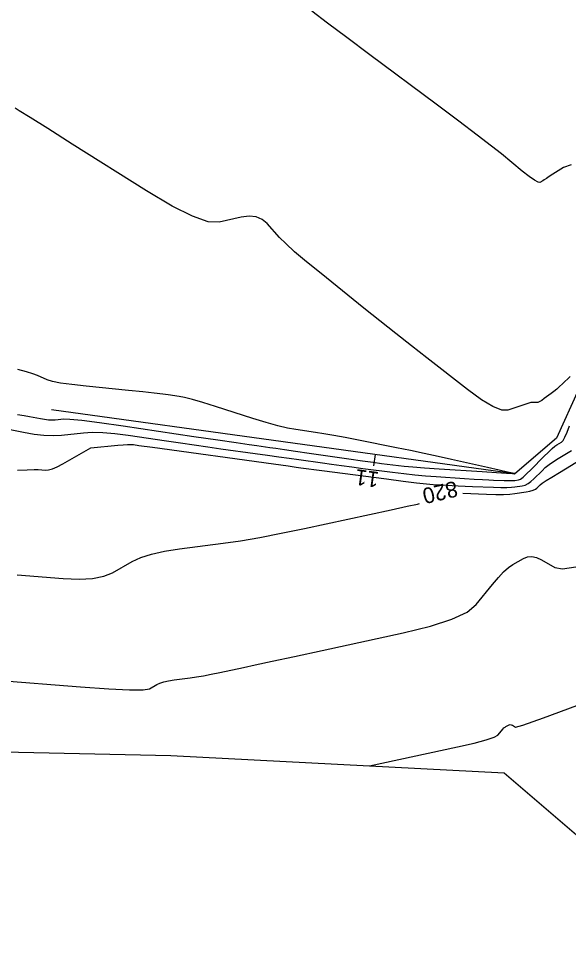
# Model space of a CAD drawing. Extents: x 1715724 to 1716561, y 394063 to 395906.
# Drawn here: x 1716135.4 to 1716184.2, y 394602.7 to 394685.4 of the extents above; entities that cross this region are included whole.
import ezdxf

# ---------------------------------------------------------------- set-up
doc = ezdxf.new("R2010")
doc.units = 0
for name, color, linetype in [('DT_X_Contour_Major', 7, 'Continuous'), ('DT_X_Contour_Minor', 7, 'Continuous'), ('DT_X_TIN_Hull', 7, 'Continuous'), ('GE_P_CL_10', 7, 'Continuous')]:
    doc.layers.add(name, color=color, linetype=linetype)

msp = doc.modelspace()

# ---------------------------------------------------------------- linework, layer by layer
at = {"layer": 'DT_X_Contour_Major'}
for points in [[(1716174.82, 394643.363), (1716176.907, 394643.286), (1716177.734, 394643.265), (1716178.431, 394643.266), (1716178.998, 394643.289), (1716179.437, 394643.336), (1716180.433, 394643.488), (1716180.773, 394643.552), (1716181.047, 394643.628), (1716181.253, 394643.716), (1716181.392, 394643.816), (1716181.673, 394644.1), (1716181.859, 394644.249), (1716182.206, 394644.485), (1716182.715, 394644.806), (1716183.385, 394645.212), (1716185.387, 394646.411)], [(1716135.281, 394636.123), (1716139.355, 394635.805), (1716140.774, 394635.747), (1716141.977, 394635.812), (1716142.962, 394636.001), (1716143.73, 394636.313), (1716145.488, 394637.308), (1716146.246, 394637.658), (1716147.2, 394637.963), (1716148.351, 394638.221), (1716149.699, 394638.432), (1716153.556, 394638.936), (1716155.091, 394639.159), (1716156.806, 394639.452), (1716158.699, 394639.814), (1716160.771, 394640.245), (1716166.535, 394641.487), (1716168.451, 394641.9), (1716169.875, 394642.207), (1716170.807, 394642.408), (1716170.976, 394642.445)]]:
    msp.add_lwpolyline(points, dxfattribs=at)
at = {"layer": 'DT_X_Contour_Minor'}
for points in [[(1716184.428, 394672.471), (1716183.743, 394672.241), (1716182.807, 394671.644), (1716182.488, 394671.441), (1716182.233, 394671.278), (1716182.042, 394671.157), (1716181.915, 394671.076), (1716181.663, 394670.916), (1716181.494, 394670.935), (1716181.175, 394671.11), (1716180.707, 394671.443), (1716180.089, 394671.932), (1716178.241, 394673.448), (1716177.36, 394674.15), (1716176.101, 394675.121), (1716174.464, 394676.36), (1716172.45, 394677.868), (1716166.575, 394682.246), (1716164.534, 394683.769), (1716162.817, 394685.053), (1716161.424, 394686.098)], [(1716184.339, 394653.715), (1716183.651, 394653.057), (1716183.396, 394652.819), (1716183.147, 394652.599), (1716182.904, 394652.398), (1716182.667, 394652.215), (1716182.042, 394651.752), (1716181.823, 394651.6), (1716181.636, 394651.491), (1716181.481, 394651.425), (1716181.358, 394651.403), (1716180.858, 394651.399), (1716178.825, 394650.733), (1716178.274, 394650.741), (1716177.493, 394651.048), (1716176.481, 394651.654), (1716175.238, 394652.56), (1716171.617, 394655.376), (1716170.251, 394656.444), (1716168.867, 394657.533), (1716167.467, 394658.645), (1716166.049, 394659.78), (1716162.245, 394662.835), (1716160.945, 394663.895), (1716159.899, 394664.784), (1716159.107, 394665.5), (1716158.569, 394666.045), (1716157.473, 394667.268), (1716157.021, 394667.648), (1716156.487, 394667.872), (1716155.87, 394667.938), (1716155.171, 394667.848), (1716153.198, 394667.397), (1716152.241, 394667.443), (1716150.851, 394667.922), (1716149.028, 394668.832), (1716146.771, 394670.174), (1716140.174, 394674.328), (1716138.001, 394675.694), (1716136.433, 394676.678), (1716135.468, 394677.28), (1716135.107, 394677.498)], [(1716135.314, 394650.349), (1716135.919, 394650.26), (1716136.37, 394650.181), (1716137.363, 394649.981), (1716137.724, 394649.919), (1716138.063, 394649.883), (1716138.378, 394649.873), (1716138.67, 394649.889), (1716139.419, 394649.966), (1716139.959, 394649.948), (1716141.017, 394649.836), (1716142.594, 394649.63), (1716144.688, 394649.329), (1716150.966, 394648.403), (1716153.079, 394648.091), (1716154.713, 394647.852), (1716155.866, 394647.684), (1716156.538, 394647.589), (1716157.691, 394647.43), (1716158.234, 394647.355), (1716158.999, 394647.246), (1716159.986, 394647.105), (1716161.194, 394646.932), (1716164.712, 394646.425), (1716165.913, 394646.253), (1716166.879, 394646.116), (1716167.609, 394646.014), (1716168.104, 394645.947), (1716169.109, 394645.816), (1716169.618, 394645.762), (1716170.39, 394645.696), (1716171.426, 394645.618), (1716172.725, 394645.53), (1716176.541, 394645.279), (1716177.793, 394645.196), (1716178.688, 394645.137), (1716179.226, 394645.102), (1716179.407, 394645.09), (1716179.412, 394645.09), (1716179.414, 394645.09), (1716179.415, 394645.09), (1716179.416, 394645.09), (1716179.417, 394645.09), (1716179.419, 394645.09), (1716179.42, 394645.091), (1716179.422, 394645.093), (1716179.426, 394645.097), (1716179.431, 394645.101), (1716179.456, 394645.126), (1716179.435, 394645.127), (1716179.43, 394645.127), (1716179.424, 394645.126), (1716179.418, 394645.124), (1716179.412, 394645.123), (1716179.393, 394645.117), (1716179.238, 394645.148), (1716178.787, 394645.247), (1716178.04, 394645.413), (1716176.996, 394645.647), (1716173.818, 394646.36), (1716172.619, 394646.625), (1716171.403, 394646.886), (1716170.172, 394647.144), (1716168.924, 394647.398), (1716165.577, 394648.07), (1716164.396, 394648.302), (1716163.366, 394648.495), (1716162.485, 394648.648), (1716161.754, 394648.762), (1716160.004, 394649.012), (1716159.274, 394649.144), (1716158.397, 394649.351), (1716157.372, 394649.633), (1716156.2, 394649.991), (1716152.878, 394651.045), (1716151.743, 394651.398), (1716150.828, 394651.666), (1716150.133, 394651.849), (1716149.659, 394651.947), (1716148.689, 394652.096), (1716148.195, 394652.163), (1716147.442, 394652.25), (1716146.428, 394652.358), (1716145.155, 394652.487), (1716141.413, 394652.858), (1716140.145, 394652.997), (1716139.146, 394653.138), (1716138.417, 394653.279), (1716137.957, 394653.421), (1716137.091, 394653.801), (1716136.681, 394653.956), (1716136.102, 394654.135), (1716135.354, 394654.339)], [(1716133.282, 394649.283), (1716135.85, 394648.767), (1716136.783, 394648.607), (1716137.657, 394648.514), (1716138.471, 394648.488), (1716139.227, 394648.529), (1716141.162, 394648.729), (1716141.955, 394648.771), (1716142.884, 394648.748), (1716143.948, 394648.659), (1716145.148, 394648.505), (1716148.528, 394648.006), (1716149.779, 394647.823), (1716151, 394647.647), (1716152.19, 394647.479), (1716153.348, 394647.318), (1716156.396, 394646.899), (1716157.495, 394646.748), (1716158.505, 394646.607), (1716159.428, 394646.477), (1716160.261, 394646.358), (1716162.368, 394646.055), (1716163.183, 394645.939), (1716164.049, 394645.819), (1716164.967, 394645.696), (1716165.935, 394645.568), (1716168.585, 394645.224), (1716169.573, 394645.103), (1716170.547, 394644.999), (1716171.508, 394644.912), (1716172.456, 394644.841), (1716174.966, 394644.676), (1716175.833, 394644.62), (1716176.552, 394644.577), (1716177.123, 394644.545), (1716177.546, 394644.527), (1716178.476, 394644.492), (1716178.797, 394644.484), (1716179.062, 394644.483), (1716179.271, 394644.49), (1716179.424, 394644.505), (1716179.757, 394644.556), (1716179.92, 394644.628), (1716180.16, 394644.803), (1716180.476, 394645.082), (1716180.869, 394645.466), (1716182.018, 394646.627), (1716182.413, 394647.018), (1716182.736, 394647.323), (1716182.988, 394647.541), (1716183.169, 394647.671), (1716183.556, 394647.902), (1716183.709, 394648.057), (1716183.878, 394648.346), (1716184.064, 394648.771), (1716184.266, 394649.331)], [(1716135.318, 394645.418), (1716136.179, 394645.454), (1716136.792, 394645.468), (1716137.156, 394645.46), (1716137.795, 394645.41), (1716138.071, 394645.431), (1716138.42, 394645.533), (1716138.843, 394645.714), (1716139.338, 394645.975), (1716141.82, 394647.38), (1716144.217, 394647.628), (1716144.689, 394647.671), (1716145.078, 394647.694), (1716145.384, 394647.697), (1716145.607, 394647.681), (1716146.089, 394647.609), (1716147.288, 394647.442), (1716158.011, 394645.968), (1716159.329, 394645.784), (1716160.023, 394645.684), (1716160.453, 394645.625), (1716162.324, 394645.378), (1716168.061, 394644.631), (1716169.527, 394644.444), (1716170.703, 394644.302), (1716171.59, 394644.205), (1716172.186, 394644.153), (1716173.391, 394644.073), (1716173.873, 394644.044), (1716174.416, 394644.016), (1716175.02, 394643.989), (1716175.685, 394643.963), (1716177.54, 394643.895), (1716178.18, 394643.877), (1716178.708, 394643.876), (1716179.125, 394643.89), (1716179.43, 394643.92), (1716180.095, 394644.022), (1716180.347, 394644.09), (1716180.603, 394644.215), (1716180.864, 394644.399), (1716181.13, 394644.641), (1716181.845, 394645.363), (1716182.136, 394645.634), (1716182.471, 394645.904), (1716182.852, 394646.173), (1716183.277, 394646.442), (1716184.471, 394647.157)], [(1716133.406, 394626.785), (1716140.915, 394626.199), (1716143.409, 394626.024), (1716145.26, 394625.938), (1716146.466, 394625.941), (1716147.029, 394626.033), (1716147.672, 394626.397), (1716147.949, 394626.525), (1716148.298, 394626.636), (1716148.719, 394626.73), (1716149.212, 394626.808), (1716150.623, 394626.992), (1716151.184, 394627.074), (1716151.811, 394627.181), (1716152.503, 394627.313), (1716153.261, 394627.471), (1716155.369, 394627.925), (1716156.398, 394628.147), (1716157.902, 394628.472), (1716159.883, 394628.9), (1716162.34, 394629.431), (1716169.526, 394630.986), (1716171.952, 394631.58), (1716173.84, 394632.196), (1716175.189, 394632.835), (1716176.001, 394633.496), (1716177.448, 394635.288), (1716177.968, 394635.901), (1716178.44, 394636.396), (1716178.865, 394636.774), (1716179.243, 394637.034), (1716180.188, 394637.571), (1716180.554, 394637.715), (1716180.943, 394637.745), (1716181.353, 394637.661), (1716181.787, 394637.463), (1716182.972, 394636.783), (1716183.658, 394636.672), (1716184.828, 394636.852)], [(1716166.528, 394619.193), (1716174.334, 394620.881), (1716175.812, 394621.216), (1716176.903, 394621.499), (1716177.606, 394621.728), (1716177.921, 394621.905), (1716178.245, 394622.305), (1716178.36, 394622.442), (1716178.466, 394622.553), (1716178.561, 394622.637), (1716178.645, 394622.695), (1716178.856, 394622.815), (1716178.938, 394622.847), (1716179.025, 394622.854), (1716179.117, 394622.835), (1716179.213, 394622.791), (1716179.478, 394622.639), (1716180.15, 394622.811), (1716181.968, 394623.442), (1716184.932, 394624.532)]]:
    msp.add_lwpolyline(points, dxfattribs=at)
at = {"layer": 'DT_X_TIN_Hull'}
msp.add_lwpolyline([(1716124.575, 394620.656), (1716148.932, 394620.106), (1716178.473, 394618.573), (1716198.368, 394601.547), (1716214.149, 394581.106), (1716226.914, 394558.689), (1716239.765, 394534.125), (1716253.999, 394509.733), (1716267.482, 394486.319), (1716281.648, 394460.466), (1716295.056, 394433.007), (1716310.248, 394404.289), (1716324.4, 394380.065), (1716338.753, 394353.428), (1716352.69, 394329.698), (1716364.178, 394305.34), (1716366.885, 394280.883)], dxfattribs=at)
at = {"layer": 'GE_P_CL_10'}
for p, q in [((1716185.108, 394652.617), (1716183.117, 394648.259)), ((1716179.417, 394645.093), (1716138.319, 394650.747)), ((1716183.117, 394648.259), (1716179.417, 394645.093)), ((1716167.035, 394646.797), (1716166.899, 394645.806))]:
    msp.add_line(p, q, dxfattribs=at)

# ---------------------------------------------------------------- texts
at = {"layer": 'DT_X_Contour_Major'}
msp.add_text('820', height=1.4, rotation=193.43254, dxfattribs=at).set_placement((1716174.167, 394644.479))
at = {"layer": 'GE_P_CL_10'}
msp.add_text('11', height=1.4, rotation=172.1668, dxfattribs=at).set_placement((1716167.447, 394645.226))

doc.saveas('drawing.dxf')
